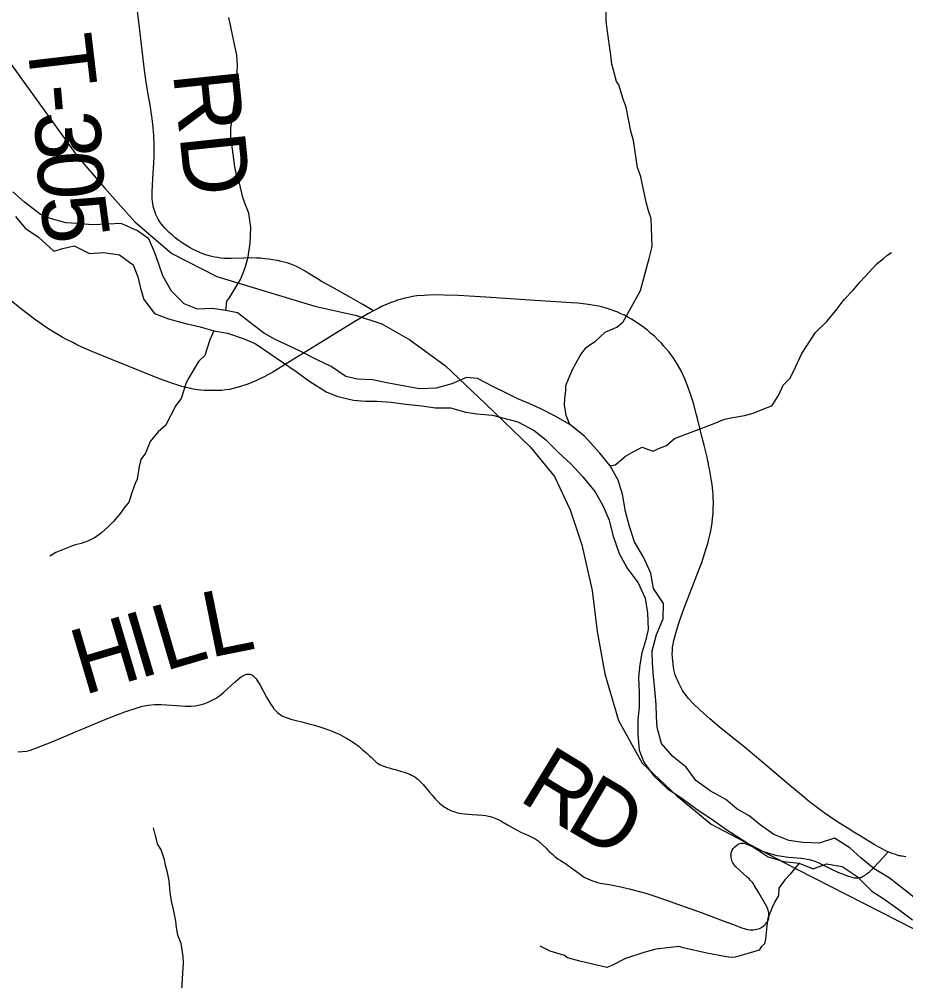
# Model space of a CAD drawing. Extents: x 0 to 34, y 0 to 22.
# Drawn here: x 6.729 to 7.499, y 14.985 to 15.821 of the extents above; entities that cross this region are included whole.
import ezdxf

# ---------------------------------------------------------------- set-up
doc = ezdxf.new("R2010")
doc.units = 0
for name, color, linetype in [('GM_X_Major_River', 7, 'Continuous'), ('GM_X_Minor_River', 7, 'Continuous'), ('GM_X_Rail_Line', 7, 'Continuous'), ('GM_X_State_Route', 7, 'Continuous'), ('GM_X_Township_Road', 7, 'Continuous'), ('GM_X_Township_Road_Text', 7, 'Continuous')]:
    doc.layers.add(name, color=color, linetype=linetype)

msp = doc.modelspace()

# ---------------------------------------------------------------- linework, layer by layer
at = {"layer": 'GM_X_Major_River'}
for points in [[(6.83165, 15.63699), (6.81754, 15.64324), (6.80541, 15.6427), (6.79215, 15.64214), (6.77925, 15.64311), (6.76938, 15.64373), (6.75682, 15.64735), (6.74729, 15.65102), (6.7335, 15.66183), (6.72314, 15.67079)], [(6.72554, 15.64934), (6.73407, 15.63926), (6.74571, 15.6315), (6.7589, 15.61909), (6.76666, 15.62142), (6.77648, 15.62373)], [(7.51255, 15.05267), (7.49837, 15.06385), (7.48496, 15.07429), (7.47196, 15.08208), (7.46046, 15.09179), (7.45086, 15.10038), (7.43748, 15.10892), (7.42427, 15.10457), (7.40985, 15.10513), (7.3977, 15.10687), (7.38474, 15.112), (7.37287, 15.12056), (7.36328, 15.12839), (7.35259, 15.13432), (7.343, 15.14253), (7.32925, 15.14993), (7.31699, 15.15887), (7.30849, 15.17051), (7.29699, 15.17984), (7.28698, 15.19108), (7.28338, 15.20506), (7.28287, 15.21454), (7.28235, 15.22515), (7.28141, 15.23841), (7.28012, 15.24939), (7.27921, 15.26113), (7.27906, 15.27175), (7.28266, 15.28583), (7.28854, 15.29956), (7.28874, 15.31284), (7.28022, 15.326), (7.27776, 15.33924), (7.27151, 15.35319), (7.26375, 15.36636), (7.25939, 15.37995), (7.2558, 15.3928), (7.25332, 15.40793), (7.24937, 15.42002), (7.24237, 15.43244), (7.2335, 15.44369), (7.22003, 15.4583), (7.20738, 15.46837), (7.19477, 15.47578), (7.18217, 15.48206), (7.17264, 15.48649), (7.16234, 15.4909), (7.1528, 15.49532), (7.14059, 15.5016), (7.12722, 15.50863), (7.11773, 15.50926), (7.10492, 15.50377), (7.09132, 15.50018), (7.07654, 15.4996), (7.06248, 15.50206), (7.04993, 15.50455), (7.03587, 15.50739), (7.02297, 15.50797), (7.0127, 15.51011), (7.00007, 15.51904), (6.9871, 15.52493), (6.97297, 15.53233), (6.96267, 15.53712), (6.95084, 15.54265), (6.94129, 15.54821), (6.9298, 15.55678), (6.91868, 15.56573), (6.90842, 15.56749), (6.89664, 15.56922), (6.88376, 15.56867), (6.87232, 15.57345), (6.86118, 15.58429), (6.85379, 15.59785), (6.85024, 15.60804), (6.8467, 15.61785), (6.8416, 15.62992), (6.83165, 15.63699)], [(6.77648, 15.62373), (6.78984, 15.61708), (6.80234, 15.61801), (6.81601, 15.61592), (6.82788, 15.60736), (6.83182, 15.59679), (6.83423, 15.58696), (6.83701, 15.57714), (6.84628, 15.56513), (6.85847, 15.56036), (6.87331, 15.55639), (6.88624, 15.55353), (6.89804, 15.5499), (6.90983, 15.54778), (6.92353, 15.54342), (6.93383, 15.53901), (6.94761, 15.52971), (6.95756, 15.52264), (6.96942, 15.51446), (6.98129, 15.50589), (6.99621, 15.49661), (7.00573, 15.49295), (7.01943, 15.48972), (7.02968, 15.48872), (7.03953, 15.48886), (7.05206, 15.48789), (7.06497, 15.48617), (7.07863, 15.48484), (7.09079, 15.4831), (7.10368, 15.4829), (7.117, 15.47928), (7.1265, 15.4779), (7.14017, 15.47656), (7.15006, 15.47404), (7.16224, 15.4708), (7.17636, 15.4634), (7.18633, 15.45557), (7.19786, 15.44397), (7.20823, 15.43425), (7.21862, 15.42301), (7.22941, 15.40989), (7.23641, 15.39746), (7.2415, 15.3854), (7.24471, 15.37217), (7.25023, 15.35631), (7.25723, 15.34351), (7.26688, 15.33075), (7.27275, 15.31756), (7.27482, 15.30469), (7.2754, 15.29028), (7.27326, 15.28039), (7.26999, 15.27011), (7.26823, 15.25985), (7.26724, 15.24884), (7.2678, 15.23557), (7.2676, 15.22267), (7.2666, 15.21204), (7.2664, 15.19914), (7.26772, 15.18551), (7.27166, 15.17494), (7.28016, 15.1633), (7.29206, 15.15208), (7.30469, 15.14353), (7.31809, 15.13385), (7.33072, 15.1253), (7.34374, 15.11599), (7.3575, 15.10746), (7.37013, 15.09891), (7.37969, 15.09259), (7.3934, 15.0886), (7.40668, 15.08727), (7.41889, 15.08212), (7.43058, 15.08645), (7.44426, 15.08436), (7.45727, 15.07543), (7.46995, 15.06271), (7.47951, 15.05677), (7.49253, 15.04747), (7.50517, 15.03778)]]:
    msp.add_lwpolyline(points, dxfattribs=at)
at = {"layer": 'GM_X_Minor_River'}
for points in [[(7.20738, 15.46837), (7.20432, 15.47643), (7.20271, 15.48566), (7.203, 15.49099), (7.20402, 15.49784), (7.20394, 15.5024), (7.20648, 15.5089), (7.20831, 15.51272), (7.21014, 15.51693), (7.21272, 15.52153), (7.21639, 15.52843), (7.22159, 15.53535), (7.22571, 15.53845), (7.22947, 15.54079), (7.23806, 15.54891), (7.24823, 15.55324), (7.25385, 15.55789), (7.26378, 15.57591), (7.26894, 15.5851), (7.27643, 15.61296), (7.27891, 15.62325), (7.27811, 15.64755), (7.27571, 15.65435), (7.27368, 15.66192), (7.26913, 15.68388), (7.26633, 15.69182), (7.26289, 15.71532), (7.26047, 15.72364), (7.25631, 15.74447), (7.25391, 15.75127), (7.2499, 15.76374), (7.24795, 15.76675), (7.2455, 15.77659), (7.24389, 15.78188), (7.243, 15.78947), (7.23995, 15.81221), (7.23907, 15.81942), (7.23869, 15.84107)], [(6.90842, 15.56749), (6.90922, 15.57564), (6.91182, 15.5791), (6.9144, 15.5837), (6.9181, 15.58946), (6.92105, 15.59444), (6.92324, 15.59942), (6.9254, 15.60591), (6.92791, 15.61431), (6.92961, 15.62611), (6.93013, 15.63979), (6.92839, 15.6523), (6.92561, 15.65948), (6.92322, 15.6659), (6.92035, 15.67839), (6.91797, 15.68405), (6.91631, 15.69239), (6.91281, 15.71892), (6.91269, 15.72614), (6.91437, 15.7387), (6.91574, 15.74708), (6.91746, 15.75737), (6.91858, 15.78056), (6.91804, 15.78967), (6.91309, 15.81277), (6.91103, 15.82223)], [(7.24237, 15.43244), (7.24689, 15.43355), (7.24951, 15.43549), (7.25587, 15.44091), (7.26188, 15.44442), (7.27016, 15.44873), (7.27398, 15.44728), (7.27971, 15.44546), (7.28385, 15.44743), (7.2914, 15.45021), (7.2985, 15.4564), (7.33282, 15.46948), (7.34187, 15.47304), (7.34905, 15.47467), (7.35928, 15.47635), (7.36683, 15.47837), (7.38342, 15.48509), (7.38895, 15.4943), (7.39298, 15.50272), (7.39858, 15.5085), (7.40189, 15.51464), (7.40921, 15.53033), (7.4166, 15.54184), (7.42104, 15.54837), (7.43075, 15.55802), (7.43967, 15.56918), (7.44598, 15.57725), (7.45381, 15.58536), (7.45976, 15.59267), (7.46721, 15.60077), (7.47429, 15.60809), (7.48028, 15.61313), (7.4829, 15.61545), (7.48703, 15.61817)], [(6.89804, 15.5499), (6.89462, 15.54198), (6.8903, 15.52861), (6.88507, 15.52359), (6.88211, 15.51899), (6.87621, 15.50902), (6.87401, 15.5048), (6.86969, 15.49106), (6.86486, 15.4849), (6.85605, 15.46767), (6.84969, 15.46225), (6.84262, 15.45378), (6.83862, 15.44346), (6.83454, 15.43808), (6.83313, 15.43197), (6.83142, 15.42093), (6.82959, 15.4171), (6.82706, 15.40985), (6.82417, 15.40106), (6.82009, 15.39606), (6.81675, 15.39145), (6.81378, 15.3876), (6.8108, 15.38413), (6.80632, 15.37988), (6.80034, 15.37447), (6.79472, 15.37021), (6.78907, 15.36746), (6.78266, 15.36507), (6.77775, 15.36386), (6.7751, 15.36306), (6.76078, 15.35713), (6.75552, 15.35401)], [(6.86995, 14.9721), (6.87113, 14.99149), (6.87174, 15.00024), (6.87126, 15.00593), (6.86954, 15.0173), (6.86676, 15.02448), (6.8655, 15.03129), (6.86503, 15.0366), (6.86296, 15.04683), (6.86133, 15.05288), (6.86049, 15.05781), (6.86004, 15.06198), (6.85911, 15.07185), (6.85784, 15.07904), (6.85583, 15.08547), (6.855, 15.09002), (6.85219, 15.09871), (6.84906, 15.10398), (6.84824, 15.10777), (6.84742, 15.11079), (6.8454, 15.11798)], [(7.40668, 15.08727), (7.39883, 15.07769), (7.39436, 15.07268), (7.38917, 15.06538), (7.3889, 15.05892), (7.38558, 15.05354), (7.38339, 15.04857), (7.37937, 15.03939), (7.37873, 15.03254), (7.37741, 15.02112), (7.37672, 15.01693), (7.3741, 15.01461), (7.37188, 15.01154), (7.36131, 15.00833), (7.3511, 15.00551), (7.3477, 15.00508), (7.34198, 15.00613), (7.32637, 15.00892), (7.30579, 15.01354), (7.30236, 15.01462), (7.28228, 15.0124), (7.27169, 15.00958), (7.25584, 15.00439), (7.2438, 14.99812), (7.23965, 14.99654), (7.2347, 14.9976), (7.21603, 15.00186), (7.20535, 15.00473), (7.20265, 15.00697), (7.19044, 15.01058), (7.18163, 15.015)]]:
    msp.add_lwpolyline(points, dxfattribs=at)
at = {"layer": 'GM_X_Rail_Line'}
msp.add_lwpolyline([(6.56024, 16.00583), (6.77959, 15.70136), (6.80293, 15.67422), (6.82944, 15.64477), (6.86151, 15.61718), (6.90063, 15.59724), (6.98568, 15.57152), (7.022, 15.56334), (7.04389, 15.55606), (7.06836, 15.54202), (7.09925, 15.51947), (7.13424, 15.48659), (7.17287, 15.44908), (7.19418, 15.42331), (7.20764, 15.39419), (7.21797, 15.36392), (7.22683, 15.32405), (7.23126, 15.2886), (7.2379, 15.25169), (7.24971, 15.21107), (7.27037, 15.17416), (7.29972, 15.14638), (7.33015, 15.121), (7.40469, 15.08186), (7.53532, 15.01541)], dxfattribs=at)
at = {"layer": 'GM_X_State_Route'}
for points in [[(7.36151, 15.18614), (7.35312, 15.19299), (7.33901, 15.20416), (7.32909, 15.21258), (7.32038, 15.22049), (7.31462, 15.22591), (7.31052, 15.23044), (7.30871, 15.23274), (7.30681, 15.23528), (7.30541, 15.23734), (7.3041, 15.23956), (7.3032, 15.2412), (7.30238, 15.24301), (7.30123, 15.24556), (7.30008, 15.24811), (7.29909, 15.25082), (7.29843, 15.2532), (7.29785, 15.25543), (7.29744, 15.25789), (7.29711, 15.26052), (7.29687, 15.26307), (7.29662, 15.26578), (7.29645, 15.26923), (7.29654, 15.27178), (7.29678, 15.27466), (7.2972, 15.27754), (7.29777, 15.28058), (7.29859, 15.28387), (7.29953, 15.28718), (7.30187, 15.29485), (7.30576, 15.30596), (7.31934, 15.34135), (7.32202, 15.34862), (7.32451, 15.35603), (7.32604, 15.36063), (7.32728, 15.36498), (7.32826, 15.36885), (7.32911, 15.37226), (7.32991, 15.37616), (7.33049, 15.37937), (7.33106, 15.38314), (7.33155, 15.38693), (7.33188, 15.39128), (7.33209, 15.39519), (7.33221, 15.40073), (7.33206, 15.40515), (7.33193, 15.40764), (7.33144, 15.41385), (7.33114, 15.41636), (7.33068, 15.41942), (7.32878, 15.42983), (7.32808, 15.43347), (7.32785, 15.43468), (7.32721, 15.43771), (7.32667, 15.44014), (7.32425, 15.4504), (7.32258, 15.45701), (7.32104, 15.463), (7.31859, 15.47262), (7.3175, 15.47682), (7.31477, 15.48704), (7.31242, 15.49481), (7.31033, 15.50069), (7.30728, 15.50823), (7.30412, 15.51504), (7.30114, 15.52056), (7.29777, 15.52585), (7.29369, 15.53141), (7.29157, 15.53409), (7.28925, 15.53668), (7.28697, 15.53923), (7.28403, 15.54209), (7.28088, 15.54518), (7.27758, 15.54802), (7.27523, 15.55012), (7.27275, 15.55201), (7.2702, 15.55403), (7.26719, 15.55606), (7.26424, 15.55813), (7.26087, 15.56014), (7.25787, 15.56194), (7.25483, 15.56349), (7.25181, 15.56481), (7.24911, 15.56607), (7.24568, 15.5674), (7.24246, 15.56862), (7.23896, 15.56964), (7.23537, 15.57067), (7.23228, 15.57139), (7.22867, 15.57204), (7.22529, 15.57262), (7.22126, 15.57319), (7.21448, 15.5739), (7.20884, 15.57438), (7.17731, 15.57642), (7.13442, 15.57916), (7.11021, 15.58053), (7.09778, 15.58105), (7.08841, 15.58118), (7.08091, 15.58076), (7.07457, 15.58025), (7.07054, 15.57967), (7.06717, 15.57893), (7.06396, 15.57827), (7.061, 15.57745), (7.05764, 15.57646), (7.05426, 15.57523), (7.0513, 15.57417), (7.04818, 15.57293), (7.0444, 15.57129), (7.04078, 15.56937), (7.03678, 15.56727), (7.03249, 15.56501), (7.02065, 15.55812), (6.99467, 15.54223), (6.96457, 15.52352), (6.94928, 15.51407), (6.94171, 15.50988), (6.93447, 15.50644), (6.9276, 15.50371), (6.92115, 15.50161), (6.91798, 15.50066), (6.91471, 15.49979), (6.91163, 15.49907), (6.90821, 15.49854), (6.90498, 15.4982), (6.9019, 15.49801), (6.89896, 15.49797), (6.89588, 15.49797), (6.89251, 15.49806), (6.88971, 15.49816), (6.88682, 15.4984), (6.88345, 15.49878), (6.87993, 15.49936), (6.8769, 15.49999), (6.87357, 15.50071), (6.8703, 15.50158), (6.86501, 15.50317), (6.86074, 15.50463), (6.85571, 15.50639), (6.85086, 15.50823), (6.79637, 15.53028), (6.79083, 15.53255), (6.78659, 15.53433), (6.78274, 15.53601), (6.77904, 15.53782), (6.77532, 15.53967), (6.77045, 15.54223), (6.76617, 15.54454), (6.7625, 15.54661), (6.75899, 15.54875), (6.75456, 15.55147), (6.75066, 15.55409), (6.74206, 15.56017), (6.73122, 15.56844), (6.7158, 15.58095)], [(7.49955, 15.09272), (7.49782, 15.09293), (7.49628, 15.09314), (7.4955, 15.09327), (7.49477, 15.09342), (7.49381, 15.09364), (7.49282, 15.09391), (7.49179, 15.09421), (7.49071, 15.09454), (7.48962, 15.09489), (7.48849, 15.09528), (7.4875, 15.09562), (7.48639, 15.09602), (7.48524, 15.09649), (7.48421, 15.0969), (7.48255, 15.09762), (7.48106, 15.09832), (7.47881, 15.09947), (7.47593, 15.10109), (7.4719, 15.1035), (7.46068, 15.11024), (7.45428, 15.1141), (7.4484, 15.11772), (7.4403, 15.12286), (7.43401, 15.12709), (7.42851, 15.13092), (7.42142, 15.13623), (7.41609, 15.14032), (7.41154, 15.14406), (7.39836, 15.15505), (7.37898, 15.17157), (7.36228, 15.18552), (7.36151, 15.18614)]]:
    msp.add_lwpolyline(points, dxfattribs=at)
at = {"layer": 'GM_X_Township_Road'}
for points in [[(7.03678, 15.56727), (7.02735, 15.5728), (7.01741, 15.57864), (7.0009, 15.58777), (6.9971, 15.58989), (6.9922, 15.59263), (6.98795, 15.59516), (6.98008, 15.60015), (6.9775, 15.60183), (6.97422, 15.60368), (6.97166, 15.60501), (6.96921, 15.60615), (6.96644, 15.60733), (6.96401, 15.60819), (6.9617, 15.60895), (6.95925, 15.60963), (6.95639, 15.61032), (6.95318, 15.61099), (6.94909, 15.61175), (6.94583, 15.6122), (6.94217, 15.61265), (6.93841, 15.61299), (6.9351, 15.61317), (6.93097, 15.61332), (6.92414, 15.61313), (6.91296, 15.61274), (6.90987, 15.61274), (6.90676, 15.61297), (6.90413, 15.61322), (6.9012, 15.61358), (6.89886, 15.61398), (6.89632, 15.61452), (6.89379, 15.61516), (6.89095, 15.61608), (6.88843, 15.61696), (6.88572, 15.61804), (6.88317, 15.61915), (6.88064, 15.6204), (6.87748, 15.62213), (6.87387, 15.62422), (6.87008, 15.62668), (6.86676, 15.62915), (6.86448, 15.63083), (6.86196, 15.63298), (6.85922, 15.63541), (6.85733, 15.63715), (6.85533, 15.63924), (6.85388, 15.64081), (6.85265, 15.64229), (6.85158, 15.64373), (6.8504, 15.64562), (6.84948, 15.6471), (6.84858, 15.64886), (6.84759, 15.651), (6.84688, 15.65286), (6.8458, 15.65642), (6.84529, 15.6584), (6.84497, 15.66067), (6.84467, 15.66259), (6.84451, 15.66428), (6.84447, 15.66584), (6.84443, 15.66827), (6.8445, 15.67053), (6.8451, 15.68227), (6.84583, 15.69585), (6.846, 15.70138), (6.84612, 15.70508), (6.84622, 15.71072), (6.8459, 15.7197), (6.84534, 15.72684), (6.84438, 15.73467), (6.84386, 15.73831), (6.84291, 15.7444), (6.84176, 15.75112), (6.8407, 15.75724), (6.83978, 15.76274), (6.83891, 15.76823), (6.838, 15.77432), (6.83557, 15.79366), (6.83308, 15.81615), (6.83079, 15.83441)], [(6.72765, 15.18403), (6.73137, 15.18414), (6.73505, 15.18463), (6.73867, 15.18551), (6.74397, 15.18729), (6.75669, 15.19231), (6.77098, 15.1984), (6.77837, 15.20164), (6.78405, 15.20406), (6.79714, 15.2095), (6.80859, 15.21412), (6.82075, 15.21872), (6.83131, 15.22233), (6.83609, 15.22364), (6.84098, 15.22453), (6.84654, 15.22502), (6.85213, 15.22504), (6.86143, 15.2245), (6.87321, 15.22363), (6.87817, 15.22364), (6.88188, 15.224), (6.88614, 15.22484), (6.89031, 15.22609), (6.89489, 15.22799), (6.89929, 15.23031), (6.90291, 15.23272), (6.90677, 15.23584), (6.91639, 15.24465), (6.91862, 15.24667), (6.92061, 15.24833), (6.92195, 15.24929), (6.92317, 15.25007), (6.92437, 15.25067), (6.92543, 15.25108), (6.92625, 15.25135), (6.92724, 15.25154), (6.92858, 15.25157), (6.92935, 15.25144), (6.93027, 15.25112), (6.93107, 15.25074), (6.93188, 15.25022), (6.93278, 15.24949), (6.9337, 15.24856), (6.93467, 15.24734), (6.93557, 15.24606), (6.93823, 15.24189), (6.94386, 15.23156), (6.94725, 15.2256), (6.94843, 15.22386), (6.94944, 15.22234), (6.95024, 15.22133), (6.95088, 15.22059), (6.9521, 15.21924), (6.9532, 15.21817), (6.95442, 15.21723), (6.95593, 15.21618), (6.95751, 15.21524), (6.95906, 15.2144), (6.96086, 15.21368), (6.96263, 15.21306), (6.96495, 15.21229), (6.96949, 15.21114), (6.9745, 15.20989), (6.98056, 15.20838), (6.98544, 15.20707), (6.99009, 15.20569), (6.99435, 15.20431), (6.99772, 15.20311), (7.00074, 15.20202), (7.00406, 15.20058), (7.00697, 15.19926), (7.0102, 15.1976), (7.0133, 15.19589), (7.01612, 15.19419), (7.01942, 15.19206), (7.02126, 15.19072), (7.02309, 15.18937), (7.02464, 15.18816), (7.02585, 15.18706), (7.02695, 15.18607), (7.0284, 15.1848), (7.02981, 15.18365), (7.03119, 15.1825), (7.0323, 15.18147), (7.03358, 15.18029), (7.03473, 15.17928), (7.03597, 15.17803), (7.03708, 15.17689), (7.03799, 15.17598), (7.03906, 15.17507), (7.03984, 15.17439), (7.04085, 15.17366), (7.04193, 15.17305), (7.04293, 15.17261), (7.04408, 15.17211), (7.04576, 15.17151), (7.04812, 15.17073), (7.05034, 15.17003), (7.0529, 15.16928), (7.05578, 15.16844), (7.05828, 15.16767), (7.06421, 15.16589), (7.06648, 15.16508), (7.06825, 15.16439), (7.06965, 15.16376), (7.07101, 15.16302), (7.07261, 15.16212), (7.07416, 15.16105), (7.07523, 15.16026), (7.07652, 15.15907), (7.07816, 15.15741), (7.07994, 15.15551), (7.08253, 15.15246), (7.08547, 15.14888), (7.08779, 15.14617), (7.09071, 15.14279), (7.09259, 15.14072), (7.09413, 15.13924), (7.09545, 15.13806), (7.09698, 15.13691), (7.09848, 15.13588), (7.10008, 15.13493), (7.10158, 15.13406), (7.1039, 15.13299), (7.10541, 15.13234), (7.10732, 15.13168), (7.10878, 15.1312), (7.11087, 15.13074), (7.11335, 15.13029), (7.11572, 15.12998), (7.1189, 15.12965), (7.12247, 15.12943), (7.13173, 15.12884), (7.13434, 15.12854), (7.13663, 15.12813), (7.13818, 15.12784), (7.14022, 15.12719), (7.14171, 15.12669), (7.14312, 15.12608), (7.14562, 15.12494), (7.14757, 15.12388), (7.14989, 15.12252), (7.1533, 15.12053), (7.15777, 15.11793), (7.16157, 15.11579), (7.16369, 15.11471), (7.16547, 15.11384), (7.16699, 15.11316), (7.16879, 15.11238), (7.17149, 15.11118), (7.17439, 15.1098), (7.17634, 15.10883), (7.17819, 15.10768), (7.17946, 15.10681), (7.18041, 15.10607), (7.18141, 15.10526), (7.18244, 15.10417), (7.1873, 15.09946), (7.18834, 15.09848), (7.18952, 15.09735), (7.19049, 15.09646), (7.19147, 15.09554), (7.19252, 15.09463), (7.19342, 15.09382), (7.19447, 15.09288), (7.19548, 15.0921), (7.19736, 15.09072), (7.19954, 15.08934), (7.20076, 15.08854), (7.20199, 15.08773), (7.20352, 15.08679), (7.2049, 15.08588), (7.20635, 15.0849), (7.20796, 15.08379), (7.21031, 15.08205), (7.21308, 15.07987), (7.21543, 15.07804), (7.21745, 15.07658), (7.21923, 15.07538), (7.22111, 15.07435), (7.223, 15.0734), (7.225, 15.07251), (7.22717, 15.07168), (7.22904, 15.07107), (7.23145, 15.07037), (7.23379, 15.06985), (7.24345, 15.06817), (7.25186, 15.0665), (7.25907, 15.06485), (7.27338, 15.06093), (7.28045, 15.05881), (7.29153, 15.05508), (7.30195, 15.05119), (7.32232, 15.04383), (7.33217, 15.04025), (7.34081, 15.03708), (7.34877, 15.03398), (7.35679, 15.03098), (7.35896, 15.03022), (7.36067, 15.02968), (7.36225, 15.02941), (7.36389, 15.02929), (7.36559, 15.02919), (7.36694, 15.02927), (7.36852, 15.02945), (7.36995, 15.02974), (7.37114, 15.03004), (7.37227, 15.03048), (7.37348, 15.03099), (7.37444, 15.03157), (7.37551, 15.03229), (7.37638, 15.03305), (7.37745, 15.03401), (7.37844, 15.03518), (7.37894, 15.03586), (7.3794, 15.03672), (7.37975, 15.03758), (7.38007, 15.03843), (7.3803, 15.03933), (7.38044, 15.04022), (7.38052, 15.04141), (7.38049, 15.04265), (7.38038, 15.04389), (7.38011, 15.04506), (7.37915, 15.04796), (7.37727, 15.05182), (7.37168, 15.06124), (7.36765, 15.06808), (7.36699, 15.06915), (7.36636, 15.07), (7.36563, 15.07086), (7.36477, 15.07176), (7.3641, 15.07248), (7.36319, 15.07338), (7.36153, 15.07492), (7.35823, 15.07799), (7.3552, 15.08069), (7.35123, 15.08453), (7.35045, 15.08542), (7.34973, 15.08645), (7.34913, 15.08748), (7.3486, 15.08858), (7.34819, 15.08961), (7.34785, 15.09087), (7.34761, 15.09204), (7.3475, 15.09324), (7.34745, 15.09405), (7.34755, 15.09502), (7.34769, 15.09594), (7.34791, 15.09677), (7.34819, 15.09759), (7.34857, 15.09843), (7.34952, 15.09997), (7.35073, 15.10131), (7.3522, 15.1025), (7.35365, 15.10353), (7.35448, 15.10396), (7.35533, 15.1043), (7.35624, 15.10449), (7.35715, 15.10458), (7.35899, 15.10442), (7.36136, 15.10371), (7.36982, 15.09982), (7.37342, 15.09825), (7.37672, 15.09702), (7.37943, 15.09606), (7.38203, 15.09529), (7.38456, 15.09454), (7.38745, 15.09393), (7.38999, 15.09339), (7.39356, 15.09283), (7.39755, 15.09237), (7.40159, 15.09199), (7.40839, 15.09143), (7.41091, 15.09113), (7.41328, 15.09071), (7.41539, 15.09027), (7.41746, 15.08971), (7.4195, 15.08908), (7.42156, 15.08835), (7.42324, 15.08768), (7.42498, 15.08693), (7.42624, 15.08628), (7.42771, 15.0855), (7.42961, 15.08456), (7.43549, 15.08169), (7.44225, 15.07859), (7.44428, 15.07773), (7.44691, 15.07675), (7.4495, 15.07576), (7.45157, 15.07517), (7.45312, 15.07478), (7.45468, 15.07445), (7.45595, 15.07432), (7.4571, 15.07432), (7.45809, 15.0744), (7.45895, 15.07453), (7.45994, 15.07478), (7.46084, 15.07506), (7.46191, 15.07552), (7.46294, 15.07609), (7.46494, 15.0774), (7.46588, 15.07815), (7.46775, 15.07973), (7.47134, 15.08314), (7.47568, 15.08759), (7.47984, 15.09214), (7.48421, 15.0969)]]:
    msp.add_lwpolyline(points, dxfattribs=at)

# ---------------------------------------------------------------- texts
at = {"layer": 'GM_X_Township_Road_Text'}
for s, height, rotation, p in [('T', 0.05682, 276.70509, (6.73486, 15.8043)), ('RD', 0.056818, 275.95675, (6.86242, 15.77405)), ('-', 0.05682, 275.00999, (6.73978, 15.76253)), ('3', 0.05682, 273.53057, (6.74179, 15.73967)), ('0', 0.05682, 273.31666, (6.74394, 15.7048)), ('5', 0.05682, 277.7716, (6.74643, 15.66506)), ('L', 0.05682, 11.38894, (6.89444, 15.26563)), ('L', 0.05682, 16.40985, (6.85494, 15.25394)), ('H', 0.05682, 16.52933, (6.78467, 15.23309)), ('I', 0.05682, 16.5347, (6.83261, 15.24731)), ('R', 0.05682, 328.66609, (7.16163, 15.14244)), ('D', 0.05682, 329.51588, (7.20226, 15.1177))]:
    msp.add_text(s, height=height, rotation=rotation, dxfattribs=at).set_placement(p)

doc.saveas('drawing.dxf')
